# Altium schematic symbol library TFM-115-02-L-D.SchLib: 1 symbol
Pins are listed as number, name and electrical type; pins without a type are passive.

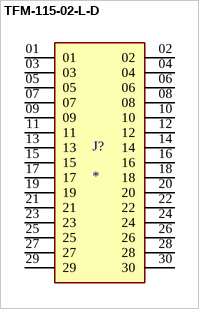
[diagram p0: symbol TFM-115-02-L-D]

## TFM-115-02-L-D
designator J?
MF: Samtec Inc.; MP: TFM-115-02-L-D
footprint SAMTEC_TFM-115-02-L-D
pins: 01, 02, 03, 04, 05, 06, 07, 08, 09, 10, 11, 12, 13, 14, 15, 16, 17, 18, 19, 20, 21, 22, 23, 24, 25, 26, 27, 28, 29, 30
